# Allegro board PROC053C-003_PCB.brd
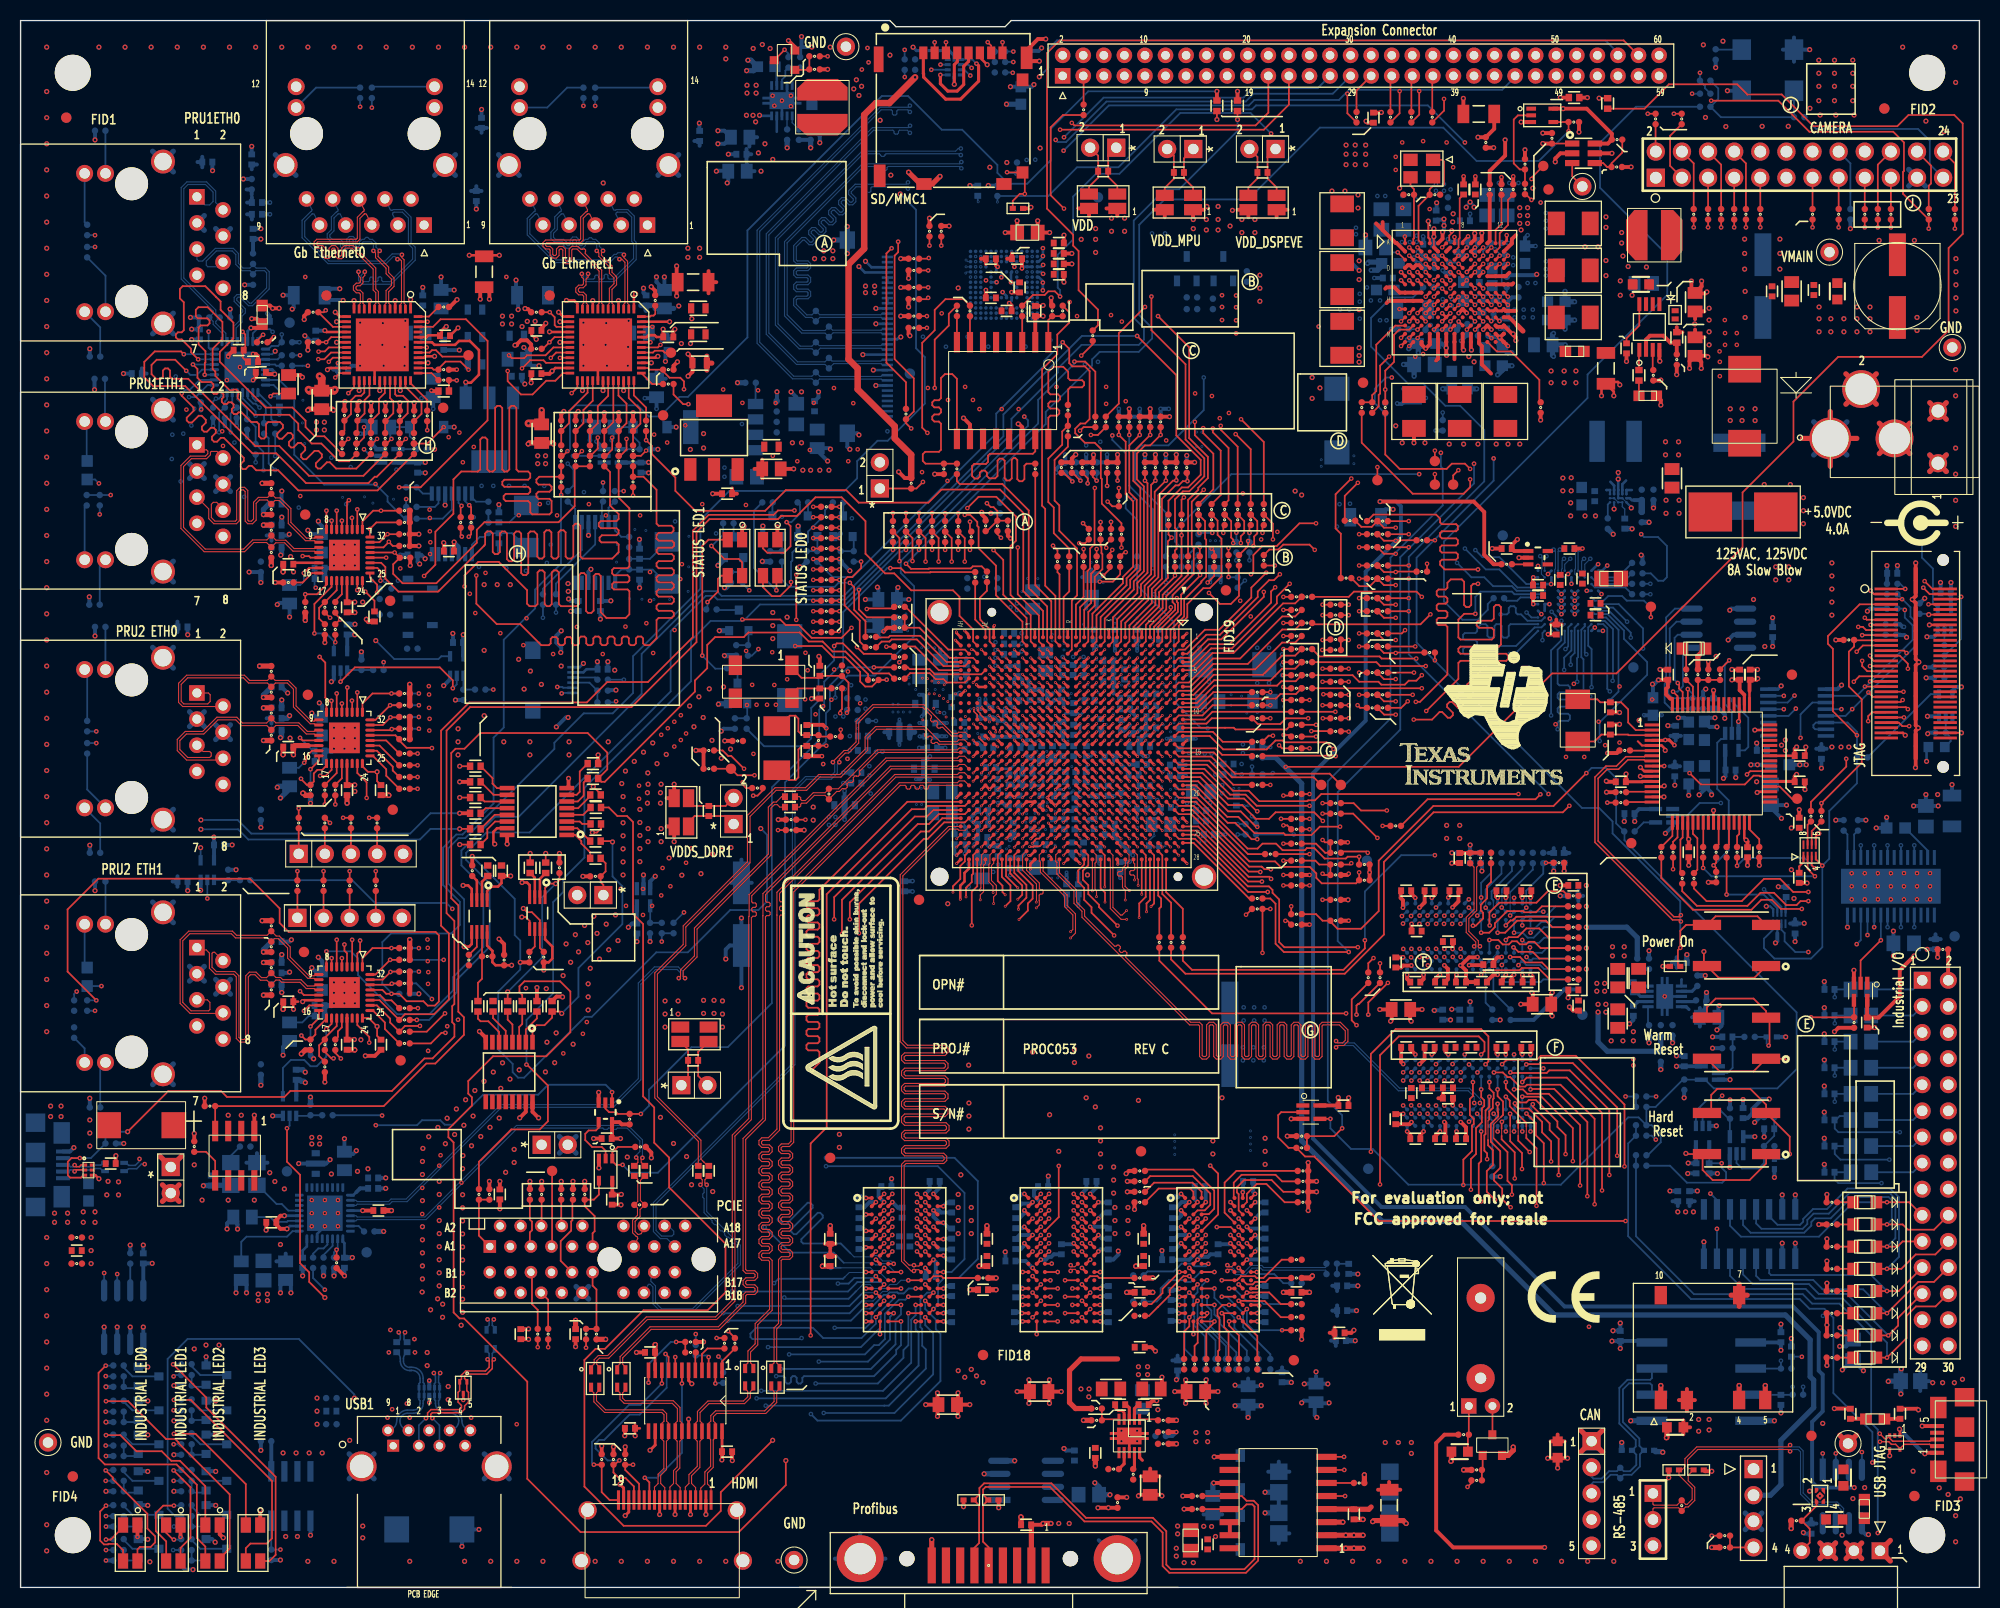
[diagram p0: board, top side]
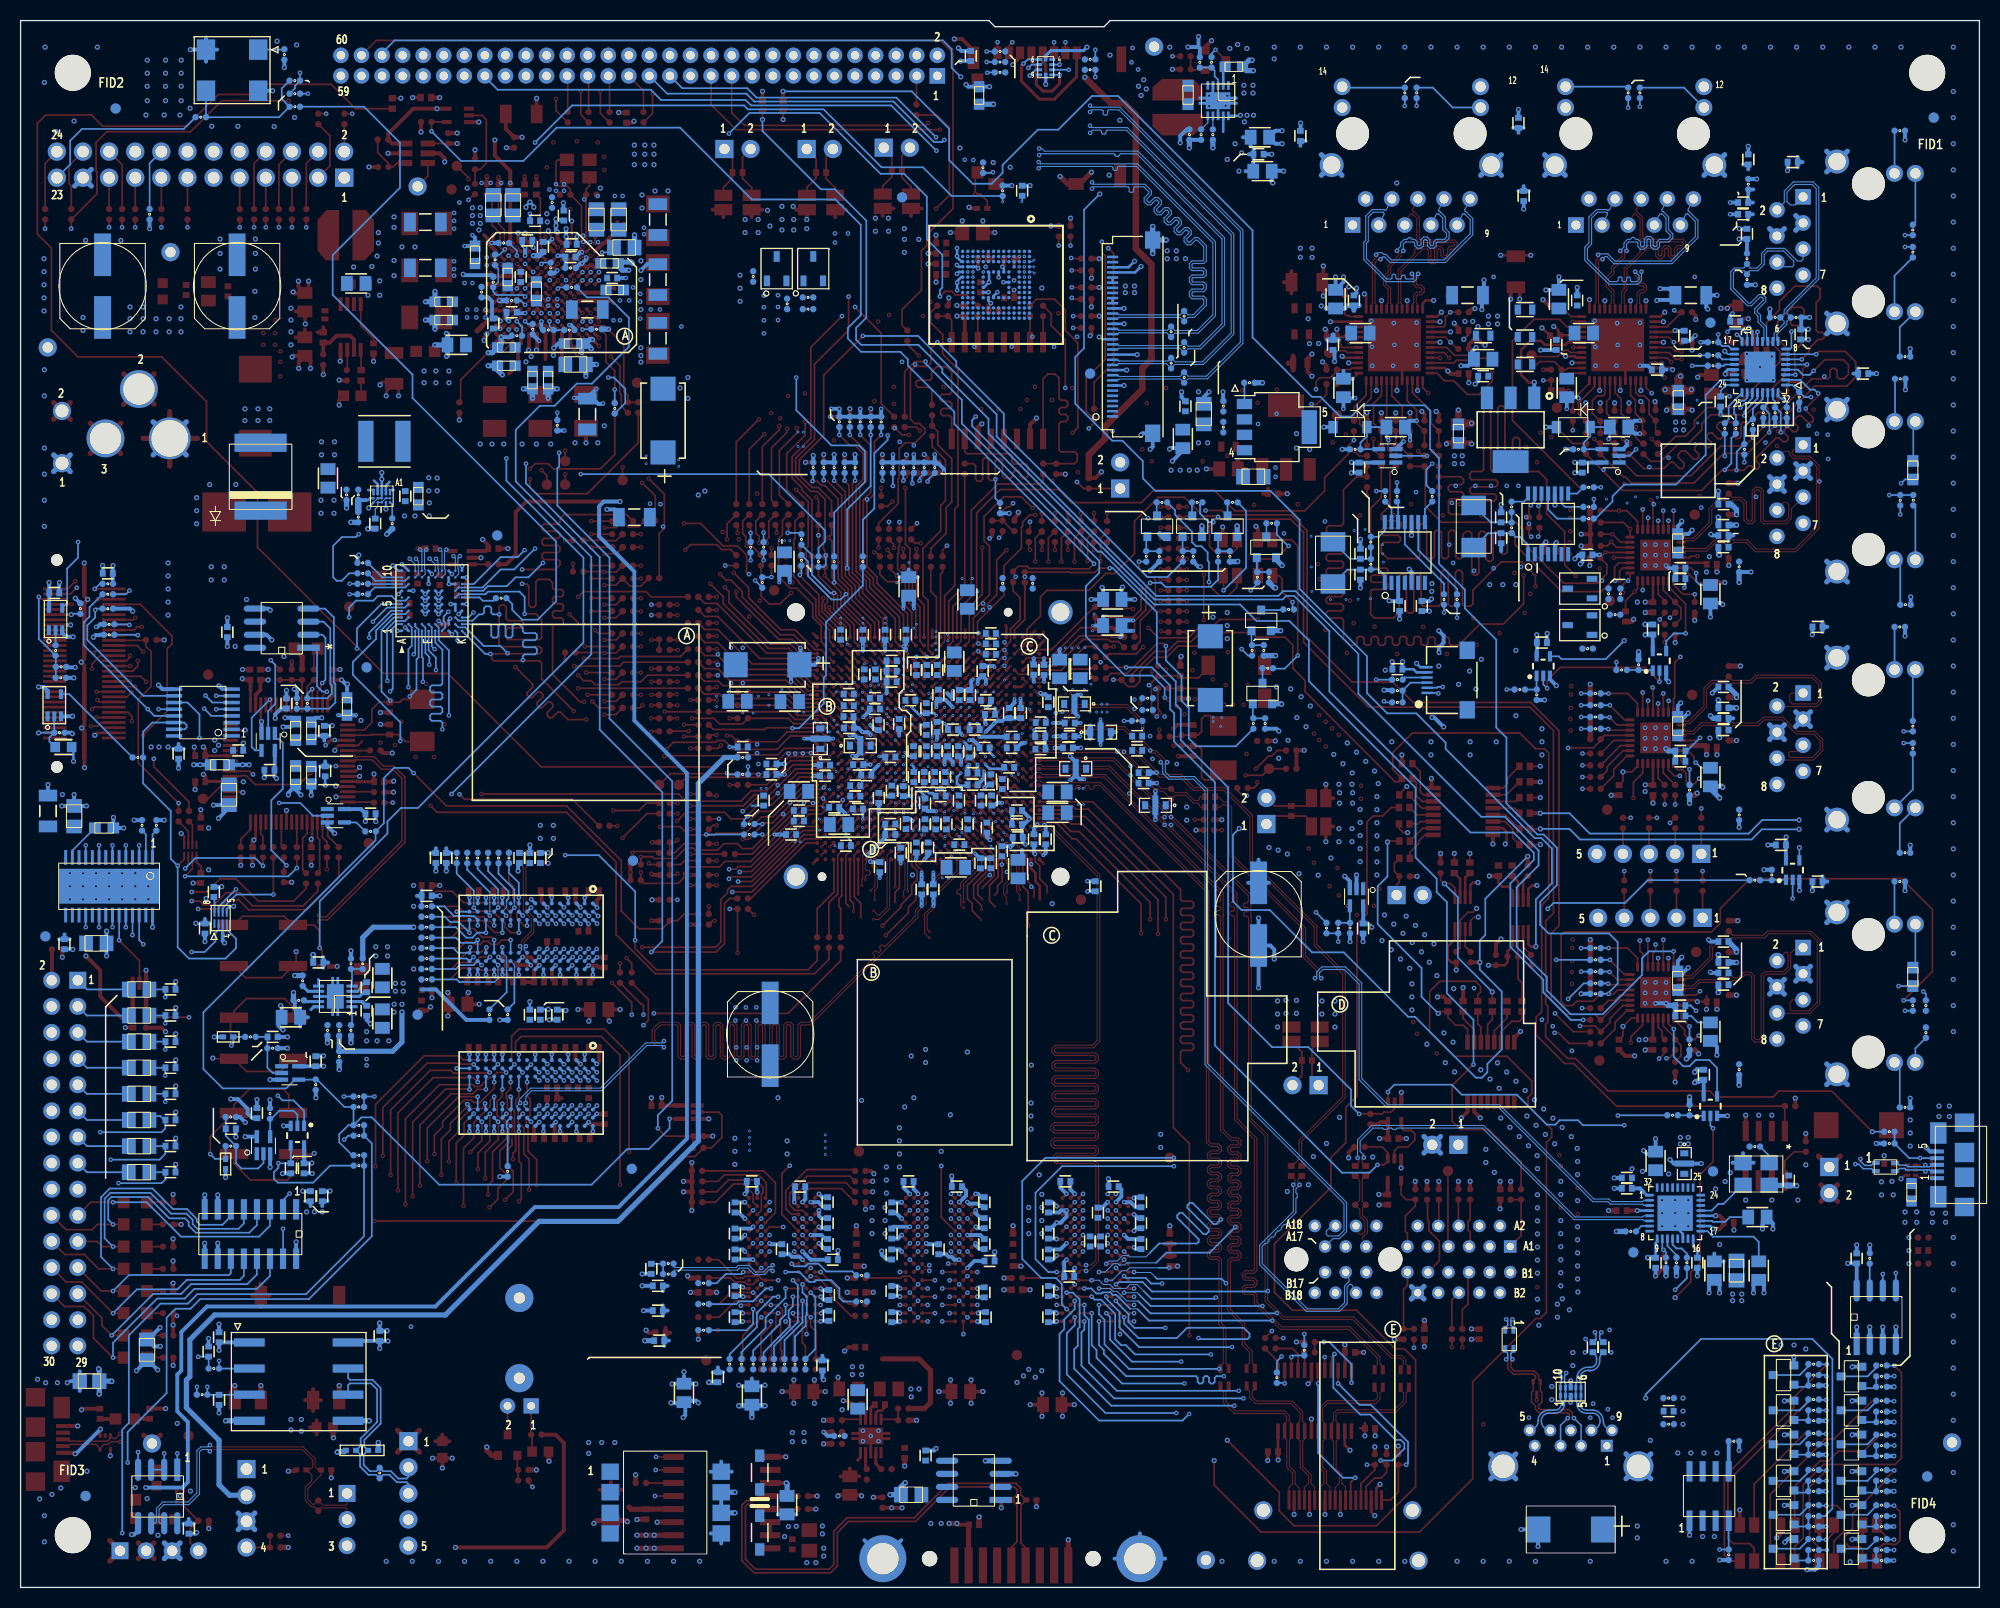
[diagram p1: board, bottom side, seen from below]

Outline 190.5 x 152.4 mm; copper layers: TOP, L2_GND1, L3_SIG1, L4_SIG2, L5_GND2, L6_PWR1, L7_PWR2, L8_GND3, L9_SIG3, L10_SIG4, L11_GND4, BOTTOM. Coordinates in mm from the lower left corner of the outline.
Outline path: 0,152.4 0,0 190.5,0 190.5,152.4 96.34,152.4 95.74,151.8 85.14,151.8 84.54,152.4 0,152.4

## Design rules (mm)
net group AM57XX_HDMI_CLK+: nets AM57XX_HDMI_CLK+ HDMI_CLK+
net group AM57XX_HDMI_CLK-: nets AM57XX_HDMI_CLK- HDMI_CLK-
net group AM57XX_HDMI_TX0+: nets AM57XX_HDMI_TX0+ HDMI_TX0+
net group AM57XX_HDMI_TX0-: nets AM57XX_HDMI_TX0- HDMI_TX0-
net group AM57XX_HDMI_TX1+: nets AM57XX_HDMI_TX1+ HDMI_TX1+
net group AM57XX_HDMI_TX1-: nets AM57XX_HDMI_TX1- HDMI_TX1-
net group AM57XX_HDMI_TX2+: nets AM57XX_HDMI_TX2+ HDMI_TX2+
net group AM57XX_HDMI_TX2-: nets AM57XX_HDMI_TX2- HDMI_TX2-
net group AM57XX_LCD_DE: nets AM57XX_LCD_DE LCD_DEN
net group AM57XX_LCD_HSYNC: nets AM57XX_LCD_HSYNC LCD_HS
net group AM57XX_LCD_PCLK: nets AM57XX_LCD_PCLK LCD_PCLK
net group AM57XX_LCD_VSYNC: nets AM57XX_LCD_VSYNC LCD_VS
net group AM57XX_MMC1_CLK: nets AM57XX_MMC1_CLK MMC_CLK
net group AM57XX_MMC1_CMD: nets AM57XX_MMC1_CMD MMC_CMD
net group AM57XX_MMC1_DAT0: nets AM57XX_MMC1_DAT0 MMC_D0
net group AM57XX_MMC1_DAT1: nets AM57XX_MMC1_DAT1 MMC_D1
net group AM57XX_MMC1_DAT2: nets AM57XX_MMC1_DAT2 MMC_D2
net group AM57XX_MMC1_DAT3: nets AM57XX_MMC1_DAT3 MMC_D3
net group AM57XX_PCIE_PER0: nets AM57XX_PCIE_PERN0 AM57XX_PCIE_PERP0
net group AM57XX_PCIE_PET0: nets AM57XX_PCIE_PETN0 AM57XX_PCIE_PETP0
net group AM57XX_PRU1ETH0_MRCLK: nets AM57XX_PRU1ETH0_MRCLK PRU1ETH0_RXCLK
net group AM57XX_PRU1ETH0_RXDV: nets AM57XX_PRU1ETH0_RXDV PRU1ETH0_RXDV
net group AM57XX_PRU1ETH1_TXCLK: nets AM57XX_PRU1ETH1_TXCLK PRU1ETH1_TXCLK
net group AM57XX_PRU1ETH1_TXD2: nets AM57XX_PRU1ETH1_TXD2 PRU1ETH1_TXD2
net group AM57XX_PRU1ETH1_TXD3: nets AM57XX_PRU1ETH1_TXD3 PRU1ETH1_TXD3
net group AM57XX_PRU1ETH1_TXEN: nets AM57XX_PRU1ETH1_TXEN PRU1ETH1_TXEN
net group AM57XX_PRU2ETH0_CRS: nets AM57XX_PRU2ETH0_CRS PRU2ETH0_CRS
net group AM57XX_PRU2ETH0_MRCLK: nets AM57XX_PRU2ETH0_MRCLK PRU2ETH0_RXCLK
net group AM57XX_PRU2ETH0_RXD0: nets AM57XX_PRU2ETH0_RXD0 PRU2ETH0_RXD0
net group AM57XX_PRU2ETH0_RXD1: nets AM57XX_PRU2ETH0_RXD1 PRU2ETH0_RXD1
net group AM57XX_PRU2ETH0_RXD2: nets AM57XX_PRU2ETH0_RXD2 PRU2ETH0_RXD2
net group AM57XX_PRU2ETH0_RXD3: nets AM57XX_PRU2ETH0_RXD3 PRU2ETH0_RXD3
net group AM57XX_PRU2ETH0_RXDV: nets AM57XX_PRU2ETH0_RXDV PRU2ETH0_RXDV
net group AM57XX_PRU2ETH0_RXER: nets AM57XX_PRU2ETH0_RXER PRU2ETH0_RXERR
net group AM57XX_PRU2ETH0_TXCLK: nets AM57XX_PRU2ETH0_TXCLK PRU2ETH0_TXCLK
net group AM57XX_PRU2ETH0_TXD0: nets AM57XX_PRU2ETH0_TXD0 PRU2ETH0_TXD0
net group AM57XX_PRU2ETH0_TXD1: nets AM57XX_PRU2ETH0_TXD1 PRU2ETH0_TXD1
net group AM57XX_PRU2ETH0_TXD2: nets AM57XX_PRU2ETH0_TXD2 PRU2ETH0_TXD2
net group AM57XX_PRU2ETH0_TXD3: nets AM57XX_PRU2ETH0_TXD3 PRU2ETH0_TXD3
net group AM57XX_PRU2ETH0_TXEN: nets AM57XX_PRU2ETH0_TXEN PRU2ETH0_TXEN
net group AM57XX_PRU2ETH1_COL: nets AM57XX_PRU2ETH1_COL PRU2ETH1_COL
net group AM57XX_PRU2ETH1_CRS: nets AM57XX_PRU2ETH1_CRS PRU2ETH1_CRS
net group AM57XX_PRU2ETH1_MRCLK: nets AM57XX_PRU2ETH1_MRCLK PRU2ETH1_RXCLK
net group AM57XX_PRU2ETH1_RXD0: nets AM57XX_PRU2ETH1_RXD0 PRU2ETH1_RXD0
net group AM57XX_PRU2ETH1_RXD1: nets AM57XX_PRU2ETH1_RXD1 PRU2ETH1_RXD1
net group AM57XX_PRU2ETH1_RXD2: nets AM57XX_PRU2ETH1_RXD2 PRU2ETH1_RXD2
net group AM57XX_PRU2ETH1_RXD3: nets AM57XX_PRU2ETH1_RXD3 PRU2ETH1_RXD3
net group AM57XX_PRU2ETH1_RXDV: nets AM57XX_PRU2ETH1_RXDV PRU2ETH1_RXDV
net group AM57XX_PRU2ETH1_RXER: nets AM57XX_PRU2ETH1_RXER PRU2ETH1_RXERR
net group AM57XX_PRU2ETH1_TXCLK: nets AM57XX_PRU2ETH1_TXCLK PRU2ETH1_TXCLK
net group AM57XX_PRU2ETH1_TXD0: nets AM57XX_PRU2ETH1_TXD0 PRU2ETH1_TXD0
net group AM57XX_PRU2ETH1_TXD1: nets AM57XX_PRU2ETH1_TXD1 PRU2ETH1_TXD1
net group AM57XX_PRU2ETH1_TXD2: nets AM57XX_PRU2ETH1_TXD2 PRU2ETH1_TXD2
net group AM57XX_PRU2ETH1_TXD3: nets AM57XX_PRU2ETH1_TXD3 PRU2ETH1_TXD3
net group AM57XX_PRU2ETH1_TXEN: nets AM57XX_PRU2ETH1_TXEN PRU2ETH1_TXEN
net group AM57XX_RGMII1_RD1: nets AM57XX_RGMII1_RD1 ETH1_RXD1
net group AM57XX_RGMII1_RD2: nets AM57XX_RGMII1_RD2 ETH1_RXD2
net group AM57XX_RTCK: nets AM57XX_RTCK RTCK
net group AM57XX_VOUT1_D0: nets AM57XX_VOUT1_D0 LCD_B0
net group AM57XX_VOUT1_D1: nets AM57XX_VOUT1_D1 LCD_B1
net group AM57XX_VOUT1_D8: nets AM57XX_VOUT1_D8 LCD_G0
net group AM57XX_VOUT1_D9: nets AM57XX_VOUT1_D9 LCD_G1
net group AM57XX_VOUT1_D16: nets AM57XX_VOUT1_D16 LCD_R0
net group AM57XX_VOUT1_D17: nets AM57XX_VOUT1_D17 LCD_R1
net group AM437X_USB1_D: nets AM574X_USB2_DM AM574X_USB2_DP
net group AM574X_QSPI_D1: nets AM574X_QSPI_D1 SPIMEM_D1
net group AM574X_VIN4B_DATA0: nets AM574X_VIN4B_DATA0 CAM1_DATA0
net group AM574X_VIN4B_DATA1: nets AM574X_VIN4B_DATA1 CAM1_DATA1
net group AM574X_VIN4B_DATA2: nets AM574X_VIN4B_DATA2 CAM1_DATA2
net group AM574X_VIN4B_DATA3: nets AM574X_VIN4B_DATA3 CAM1_DATA3
net group AM574X_VIN4B_DATA4: nets AM574X_VIN4B_DATA4 CAM1_DATA4
net group AM574X_VIN4B_DATA5: nets AM574X_VIN4B_DATA5 CAM1_DATA5
net group AM574X_VIN4B_DATA6: nets AM574X_VIN4B_DATA6 CAM1_DATA6
net group AM574X_VIN4B_DATA7: nets AM574X_VIN4B_DATA7 CAM1_DATA7
net group AM574X_VIN4B_HSYNC: nets AM574X_VIN4B_HSYNC CAM1_HSYNC
net group AM574X_VIN4B_PCLK: nets AM574X_VIN4B_PCLK CAM1_PCLK
net group AM574X_VIN4B_VSYNC: nets AM574X_VIN4B_VSYNC CAM1_VSYNC
net group ETH_MDIO_CLK: nets ETH_MDIO_CLK PRU1ETH0_COL
net group JTAG_TCK: nets JTAG_TCK TCK
net group PCI_CONN_REF: nets PCI_CONN_REFN PCI_CONN_REFP
net group SERDES_REF_CLK: nets SERDES_REF_CLKN SERDES_REF_CLKP
net group SPIMEM_CSN: nets AM574X_QSPI_CSN SPIMEM_CSN
net group SPIMEM_D0: nets AM574X_QSPI_D0 SPIMEM_D0
net group SPIMEM_D2: nets AM574X_QSPI_D2 SPIMEM_D2
net group SPIMEM_D3: nets AM574X_QSPI_D3 SPIMEM_D3
net group AM57XX_PRU1ETH1_MRCLK: nets AM57XX_PRU1ETH1_MRCLK ETH1_TXD3 PRU1ETH1_RXCLK
net group AM57XX_PRU1ETH1_TXD0: nets AM57XX_PRU1ETH1_TXD0 ETH1_TXEN PRU1ETH1_TXD0
net group AM57XX_PRU1ETH1_TXD1: nets AM57XX_PRU1ETH1_TXD1 ETH1_TXCLK PRU1ETH1_TXD1
net group AM57XX_PRU1ETH_MDCLK: nets AM57XX_PRU1ETH_MDCLK PRU1ETH0_MDC PRU1ETH1_MDC
net group AM57XX_PRU1ETH_MDDATA: nets AM57XX_PRU1ETH_MDDATA PRU1ETH0_MDIO PRU1ETH1_MDIO
net group AM57XX_PRU2ETH_MDCLK: nets AM57XX_PRU2ETH_MDCLK PRU2ETH0_MDC PRU2ETH1_MDC
net group AM57XX_PRU2ETH_MDDATA: nets AM57XX_PRU2ETH_MDDATA PRU2ETH0_MDIO PRU2ETH1_MDIO
net group AM57XX_RGMII0_RD0: nets AM57XX_RGMII0_RD0 ETH0_RXD0 PRU1ETH0_TXD0
net group AM57XX_RGMII0_RD1: nets AM57XX_RGMII0_RD1 ETH0_RXD1 PRU1ETH0_TXD1
net group AM57XX_RGMII0_RD2: nets AM57XX_RGMII0_RD2 ETH0_RXD2 PRU1ETH0_TXEN
net group AM57XX_RGMII0_RD3: nets AM57XX_RGMII0_RD3 ETH0_RXD3 PRU1ETH0_TXD2
net group AM57XX_RGMII0_RXCLK: nets AM57XX_RGMII0_RXCLK ETH0_RXCLK PRU1ETH0_TXCLK
net group AM57XX_RGMII0_RXCTL: nets AM57XX_RGMII0_RXCTL ETH0_RXDV PRU1ETH0_TXD3
net group AM57XX_RGMII0_TD0: nets AM57XX_RGMII0_TD0 ETH0_TXD0 PRU1ETH0_RXD0
net group AM57XX_RGMII0_TD1: nets AM57XX_RGMII0_TD1 ETH0_TXD1 PRU1ETH0_RXD1
net group AM57XX_RGMII0_TD2: nets AM57XX_RGMII0_TD2 ETH0_TXD2 PRU1ETH0_RXERR
net group AM57XX_RGMII0_TD3: nets AM57XX_RGMII0_TD3 ETH0_TXD3 PRU1ETH0_CRS
net group AM57XX_RGMII0_TXCLK: nets AM57XX_RGMII0_TXCLK ETH0_TXCLK PRU1ETH0_RXD3
net group AM57XX_RGMII0_TXCTL: nets AM57XX_RGMII0_TXCTL ETH0_TXEN PRU1ETH0_RXD2
net group AM57XX_RGMII1_RD0: nets AM57XX_RGMII1_RD0 ETH1_RXD0 PRU1ETH1_CRS
net group AM57XX_RGMII1_RD3: nets AM57XX_RGMII1_RD3 ETH1_RXD3 PRU1ETH1_RXERR
net group AM57XX_RGMII1_RXCLK: nets AM57XX_RGMII1_RXCLK ETH1_RXCLK PRU1ETH1_RXD1
net group AM57XX_RGMII1_RXCTL: nets AM57XX_RGMII1_RXCTL ETH1_RXDV PRU1ETH1_RXD0
net group AM57XX_RGMII1_TD0: nets AM57XX_RGMII1_TD0 ETH1_TXD0 PRU1ETH1_RXD2
net group AM57XX_RGMII1_TD1: nets AM57XX_RGMII1_TD1 ETH1_TXD1 PRU1ETH1_RXD3
net group AM57XX_RGMII1_TD2: nets AM57XX_RGMII1_TD2 ETH1_TXD2 PRU1ETH1_RXDV
net group AM57XX_VOUT1_D2: nets AM57XX_VOUT1_D2 EMU2 LCD_B2
net group AM57XX_VOUT1_D3: nets AM57XX_VOUT1_D3 EMU5 LCD_B3
net group AM57XX_VOUT1_D4: nets AM57XX_VOUT1_D4 EMU6 LCD_B4
net group AM57XX_VOUT1_D5: nets AM57XX_VOUT1_D5 EMU7 LCD_B5
net group AM57XX_VOUT1_D6: nets AM57XX_VOUT1_D6 EMU8 LCD_B6
net group AM57XX_VOUT1_D7: nets AM57XX_VOUT1_D7 EMU9 LCD_B7
net group AM57XX_VOUT1_D10: nets AM57XX_VOUT1_D10 EMU3 LCD_G2
net group AM57XX_VOUT1_D11: nets AM57XX_VOUT1_D11 EMU10 LCD_G3
net group AM57XX_VOUT1_D12: nets AM57XX_VOUT1_D12 EMU11 LCD_G4
net group AM57XX_VOUT1_D13: nets AM57XX_VOUT1_D13 EMU12 LCD_G5
net group AM57XX_VOUT1_D14: nets AM57XX_VOUT1_D14 EMU13 LCD_G6
net group AM57XX_VOUT1_D15: nets AM57XX_VOUT1_D15 EMU14 LCD_G7
net group AM57XX_VOUT1_D18: nets AM57XX_VOUT1_D18 EMU4 LCD_R2
net group AM57XX_VOUT1_D19: nets AM57XX_VOUT1_D19 EMU15 LCD_R3
net group AM57XX_VOUT1_D20: nets AM57XX_VOUT1_D20 EMU16 LCD_R4
net group AM57XX_VOUT1_D21: nets AM57XX_VOUT1_D21 EMU17 LCD_R5
net group AM57XX_VOUT1_D22: nets AM57XX_VOUT1_D22 EMU18 LCD_R6
net group AM57XX_VOUT1_D23: nets AM57XX_VOUT1_D23 EMU19 LCD_R7
net group CLK: nets AM57XX_CLKOUT3 AM57XX_OSC0_IN AM57XX_OSC0_OUT ETH0GB_25MHZCLK ETH1GB_25MHZCLK INDUS_INPUTCLK N17745710 N22642197 OSC0_OUT PRU1ETH0_25MHZCLK PRU1ETH1_25MHZCLK PRU2ETH0_25MHZCLK PRU2ETH1_25MHZCLK SRCCLK XTIN XTOUT
net group DDR_ADD: nets DDR_CKE
net group PWR: nets ETH0_LDO_O N11219802 N11219922 N18915671 N18915723 N19923825 N19923832 N19923845 N19923851 N19923852 N19923865 N20287248 N21553219 N21553307 N21553371 N22644059 USB1_OVRCURN V5_0DFB VANA_OUT VLDO1_OUT VPP_CONN
net group SPIMEM_CLK: nets AM574X_QSPI_CLK AM574X_QSPI_RTCLK QSPI_CLK SPIMEM_CLK
nets with their own width: min track width 0.127; nets DGND
nets with their own width: min track width 0.381; nets VSDMMC

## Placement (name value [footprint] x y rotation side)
C1  18 pF  [CC0402]  76.45 83.39 90 top
C1_1  1uF  [CC0603]  177.27 10.68 90 top
C2  18 pF  [CC0402]  76.45 81.36 270 top
C2_1  1uF  [CC0603]  176.38 6.62 0 top
C3  10000pF  [CC0402]  167.51 46.14 90 bottom
C4  1uF  [CC0402]  170.05 44.61 180 bottom
C5  1uF  [CC0402]  165.99 53.55 180 bottom
C6  10uF  [CC0805]  93.49 69.87 270 bottom
C7  10000pF  [CC0402]  93.52 72.95 180 bottom
C8  10000pF  [CC0402]  93.6 74.22 180 bottom
C9  10000pF  [CC0402]  95.07 71.61 270 bottom
C10  10000pF  [CC0402]  97.16 70.44 270 bottom
C11  10000pF  [CC0402]  93.6 75.57 180 bottom
C12  10000pF  [CC0402]  90.8 72.77 90 bottom
C13  10uF  [CC0805]  110.9 74.2 0 bottom
C14  10000pF  [CC0402]  103.38 71.96 270 bottom
C15  10000pF  [CC0402]  110.24 72.14 0 bottom
C16  10000pF  [CC0402]  109.07 75.72 0 bottom
C17  10000pF  [CC0402]  102.23 71.96 270 bottom
C20  0.1uF  [CC0402]  170.33 126.07 90 top
C21  0.1uF  [CC0402]  174.4 126.19 90 top
C22  10uF  [CC0805]  172.24 126.07 90 top
C23  1uF  [CC0603]  176.68 126.07 90 top
C24  100uF  [SM-7351-CAP-SMDCAN]  169.44 126.57 270 bottom
C25  27pF  [SM-7351-CAP-0402]  135 135.46 0 top
C26  27pF  [SM-7351-CAP-0402]  137.54 135.46 180 top
C27  0.1uF  [CC0402]  140.34 135.97 270 top
C28  10000pF  [CC0402]  98.68 124.16 90 top
C29  10000pF  [CC0402]  81.53 35.43 270 bottom
C30  10000pF  [CC0402]  84.2 38.99 0 bottom
C31  10000pF  [CC0402]  81.53 37.46 270 bottom
C32  10000pF  [CC0402]  90.55 36.96 90 bottom
C33  22uF  [CC0805]  90.17 17.78 0 top
C34  10000pF  [CC0402]  88.9 39.5 0 bottom
C35  10000pF  [CC0402]  90.55 26.29 270 bottom
C36  10000pF  [CC0402]  90.55 32.38 90 bottom
C37  10000pF  [CC0402]  90.55 28.83 90 bottom
C38  10000pF  [CC0402]  90.55 34.42 270 bottom
C39  10000pF  [CC0402]  88.52 30.23 0 bottom
C40  10000pF  [CC0402]  85.47 33.66 90 bottom
C41  10000pF  [CC0402]  85.72 36.45 90 bottom
C42  10000pF  [CC0402]  81.53 33.4 270 bottom
C43  10000pF  [CC0402]  86.49 33.66 90 bottom
C44  0.1uF  [CC0402]  78.74 33.91 270 top
C45  0.1uF  [CC0402]  78.74 31.75 270 top
C46  0.1uF  [CC0402]  93.6 28.96 0 top
C47  0.1uF  [CC0402]  109.22 33.91 270 top
C48  10000pF  [CC0402]  105.79 36.96 90 bottom
C49  10000pF  [CC0402]  96.77 37.46 270 bottom
C50  10000pF  [CC0402]  104.14 39.5 0 bottom
C51  10000pF  [CC0402]  96.65 26.29 270 bottom
C52  22uF  [CC0805]  99.06 19.05 0 top
C53  0.1uF  [CC0402]  109.22 31.75 270 top
C54  0.1uF  [CC0402]  124.08 28.7 0 top
C55  10000pF  [CC0402]  105.79 26.29 270 bottom
C56  10000pF  [CC0402]  96.27 31.75 180 bottom
C57  10000pF  [CC0402]  96.77 28.7 90 bottom
C58  10000pF  [CC0402]  101.22 32.89 270 bottom
C59  10000pF  [CC0402]  96.77 33.4 270 bottom
C60  10000pF  [CC0402]  111.51 31.88 180 bottom
C61  10000pF  [CC0402]  121.03 32.38 270 bottom
C62  10000pF  [CC0402]  116.46 32.89 270 bottom
C63  10000pF  [CC0402]  119.38 39.5 0 bottom
C64  22uF  [CC0805]  114.3 19.05 0 top
C65  10000pF  [CC0402]  105.79 32.38 270 bottom
C66  10000pF  [CC0402]  105.79 28.83 90 bottom
C67  10000pF  [CC0402]  96.77 35.43 270 bottom
C68  10000pF  [CC0402]  105.79 34.42 270 bottom
C69  10000pF  [CC0402]  99.44 38.99 0 bottom
C70  10000pF  [CC0402]  121.03 26.29 270 bottom
C71  10000pF  [CC0402]  114.68 38.99 0 bottom
C72  10000pF  [CC0402]  111.89 26.42 270 bottom
C73  10000pF  [CC0402]  121.03 34.42 270 bottom
C74  10000pF  [CC0402]  112.01 37.46 270 bottom
C75  10000pF  [CC0402]  121.03 28.83 90 bottom
C76  10000pF  [CC0402]  121.03 36.96 90 bottom
C77  10000pF  [CC0402]  112.01 35.43 270 bottom
C78  10000pF  [CC0402]  112.01 33.4 270 bottom
C79  10000pF  [CC0402]  111.89 28.45 90 bottom
C80  0.1uF  [CC0402]  93.98 33.91 270 top
C81  10000pF  [CC0402]  96.14 78.59 90 bottom
C82  0.1uF  [CC0402]  93.98 31.75 270 top
C83  0.1uF  [CC0402]  108.84 28.7 0 top
C84  0.001uF  [SM-7351-CAP-0402]  110.87 14.73 180 bottom
C85  0.1uF  [CC0402]  129.16 30.99 270 bottom
C86  0.001uF  [SM-7351-CAP-0402]  111.12 16.26 0 top
C87  0.1uF  [CC0402]  128.52 29.34 0 bottom
C88  10uF  [CC0805]  109.86 9.91 270 top
C89  0.1uF  [CC0402]  128.27 24.77 0 top
C90  0.1uF  [CC0402]  109.22 17.78 0 top
C91  10uF  [CC0805]  109.98 19.3 0 top
C92  10uF  [CC0805]  109.09 18.29 270 bottom
C93  0.1uF  [CC0402]  108.84 23.37 0 top
C94  0.1uF  [CC0402]  112.52 21.59 270 bottom
C95  10uF  [CC0805]  125.98 18.92 270 bottom
C96  10uF  [CC0805]  119.38 18.67 270 bottom
C97  10uF  [CC0805]  106.05 19.3 180 top
C98  0.1uF  [CC0402]  128.4 24 0 bottom
C99  0.1uF  [CC0402]  104.52 13.08 270 top
C100  0.1uF  [CC0402]  106.93 17.78 180 top
C101  10pF  [SM-7351-CAP-0402]  104.65 16.26 180 top
C102  0.1uF  [CC0402]  22.99 134.7 0 bottom
C103  0.1uF  [CC0402]  22.99 133.56 0 bottom
C104  0.1uF  [CC0402]  17.4 121.87 270 bottom
C105  10000pF  [CC0402]  23.37 118.19 180 top
C106  4700pF  [CC0402]  18.16 138.64 180 bottom
C107  0.1uF  [CC0402]  22.61 131.65 90 bottom
C108  0.1uF  [CC0402]  25.17 115.35 270 bottom
C109  0.1uF  [CC0402]  22.61 119.21 0 top
C110  10uF  [CC0805]  26.06 117.02 90 top
C111  0.1uF  [CC0402]  21.21 120.35 180 top
C112  10000pF  [CC0402]  23.75 123.14 0 bottom
C113  10000pF  [CC0402]  42.55 91.9 180 bottom
C114  10000pF  [CC0402]  97.92 79.2 180 bottom
C115  10000pF  [CC0402]  96.14 70.44 270 bottom
C116  0.1uF  [CC0402]  24.89 102.32 0 bottom
C117  0.1uF  [CC0402]  24.89 101.17 0 bottom
C118  10000pF  [CC0402]  26.03 99.52 180 top
C119  0.1uF  [CC0402]  24.89 105.36 0 bottom
C120  10000pF  [CC0402]  31.75 95.33 270 top
C121  4700pF  [CC0402]  11.3 118.06 0 bottom
C122  0.1uF  [CC0402]  24.89 103.33 0 bottom
C123  0.1uF  [CC0402]  34.42 94.44 270 top
C124  0.1uF  [CC0402]  29.08 99.14 0 bottom
C125  10uF  [CC0805]  26.16 96.6 270 bottom
C126  0.1uF  [CC0402]  29.08 98.13 0 bottom
C127  10000pF  [CC0402]  31.75 93.17 90 bottom
C128  0.1uF  [CC0402]  24.89 84.54 0 bottom
C129  0.1uF  [CC0402]  24.89 83.39 0 bottom
C130  10000pF  [CC0402]  31.75 77.55 270 top
C131  4700pF  [CC0402]  15.75 93.43 180 bottom
C132  0.1uF  [CC0402]  24.89 85.55 0 bottom
C133  0.1uF  [CC0402]  24.89 87.58 0 bottom
C134  0.1uF  [CC0402]  29.08 80.35 0 bottom
C135  0.1uF  [CC0402]  35.05 77.55 270 top
C136  10uF  [CC0805]  26.16 78.82 270 bottom
C137  10000pF  [CC0402]  26.03 81.74 180 top
C138  0.1uF  [CC0402]  29.08 81.36 0 bottom
C139  10000pF  [CC0402]  19.3 72.22 0 bottom
C140  0.1uF  [CC0402]  24.89 59.77 0 bottom
C141  0.1uF  [CC0402]  24.89 58.63 0 bottom
C142  10000pF  [CC0402]  26.03 56.98 180 top
C143  0.1uF  [CC0402]  24.89 60.79 0 bottom
C144  10000pF  [CC0402]  31.75 52.79 270 top
C145  0.1uF  [CC0402]  24.89 62.82 0 bottom
C146  4700pF  [CC0402]  15.75 68.66 180 bottom
C147  0.1uF  [CC0402]  35.05 52.79 270 top
C148  0.1uF  [CC0402]  29.08 56.6 0 bottom
C149  10uF  [CC0805]  26.16 54.06 270 bottom
C150  0.1uF  [CC0402]  29.08 55.58 0 bottom
C151  10000pF  [CC0402]  26.8 49.87 90 bottom
C152  10000pF  [CC0402]  131.57 142.96 90 top
C153  0.1uF  [CC0402]  48.26 117.81 0 bottom
C154  10uF  [CC0805]  48.26 119.46 0 bottom
C155  0.1uF  [CC0402]  28.7 121.75 270 bottom
C156  10uF  [CC0805]  29.29 115.5 270 top
C157  47uF  [CC1206]  28.07 125.68 0 bottom
C158  47uF  [CC1206]  45.09 127.97 90 top
C159  10uF  [CC0805]  40.13 116.67 270 bottom
C160  0.1uF  [CC0402]  31.37 118.45 0 bottom
C161  10uF  [CC0805]  40.89 125.3 90 bottom
C162  0.1uF  [CC0402]  39.12 125.18 90 bottom
C163  10uF  [CC0805]  38.48 122 180 bottom
C164  0.1uF  [CC0402]  41.15 120.86 270 bottom
C165  10000pF  [CC0402]  41.27 121.75 0 top
C166  0.1uF  [CC0402]  22.48 138.89 270 bottom
C167  0.1uF  [CC0402]  44.32 135.34 90 bottom
C168  10uF  [CC0805]  35.05 112.86 180 bottom
C169  10000pF  [CC0402]  41.66 100.79 180 top
C170  10000pF  [CC0402]  38.13 100.44 180 bottom
C171  10000pF  [CC0402]  38.61 108.92 270 bottom
C172  18pF  [CC0402]  46.51 102.05 90 bottom
C173  18pF  [CC0402]  46.51 104.08 270 bottom
C174  0.1uF  [CC0402]  50.16 122.26 180 top
C175  10uF  [CC0805]  50.67 112.22 270 top
C176  0.1uF  [CC0402]  68.71 106.38 180 top
C177  10uF  [CC0805]  73.02 108.79 0 top
C178  47uF  [CC1206]  49.78 125.68 180 bottom
C179  47uF  [CC1206]  65.41 126.95 180 top
C180  10uF  [CC0805]  61.85 116.67 270 bottom
C181  0.1uF  [CC0402]  50.16 118.06 180 top
C182  10uF  [CC0805]  62.61 125.3 90 bottom
C183  0.1uF  [CC0402]  60.83 125.18 90 bottom
C184  10uF  [CC0805]  60.2 122 180 bottom
C185  0.1uF  [CC0402]  62.86 120.86 270 bottom
C186  10000pF  [CC0402]  62.99 121.62 0 top
C187  0.1uF  [CC0402]  44.83 142.45 270 bottom
C188  0.1uF  [CC0402]  66.04 141.18 270 bottom
C189  10uF  [CC0805]  56.77 112.86 180 bottom
C190  10000pF  [CC0402]  56.39 95.46 270 bottom
C191  10000pF  [CC0402]  54.23 95.46 270 bottom
C192  10000pF  [CC0402]  60.32 108.92 270 bottom
C193  18pF  [CC0402]  60.2 98.51 90 bottom
C194  18pF  [CC0402]  60.2 100.54 270 bottom
C195  10000pF  [CC0402]  179.58 54.95 270 top
C196  0.001uF  [SM-7351-CAP-0402]  186.94 62.06 180 top
C197  0.022uF  [CC0402]  175.92 58.17 180 bottom
C198  0.022uF  [CC0402]  175.92 55.63 180 bottom
C199  0.022uF  [CC0402]  175.92 53.09 180 bottom
C200  0.022uF  [CC0402]  175.92 50.55 180 bottom
C201  0.022uF  [CC0402]  175.92 48.01 180 bottom
C202  0.022uF  [CC0402]  175.92 45.47 180 bottom
C203  0.022uF  [CC0402]  175.92 42.93 180 bottom
C204  0.022uF  [CC0402]  175.92 40.39 180 bottom
C205  2.2uF  [SM-7351-CAP-0805]  183.13 62.65 180 bottom
C206  10uF  [CC1206]  187.83 75.52 90 bottom
C207  10000pF  [CC0402]  186.23 62.57 270 bottom
C208  2.2uF  [SM-7351-CAP-0805]  178.21 23.11 90 bottom
C209  1uF  [CC0402]  161.16 38.05 90 bottom
C210  10000pF  [CC0402]  162.31 38.05 90 bottom
C211  0.1uF  [CC0402]  98.08 148.96 270 bottom
C212  4.7uF  [SM-7351-CAP-0603]  97.28 145.12 270 bottom
C213  0.1uF  [CC0402]  164.21 40.77 270 bottom
C214  10000pF  [CC0402]  128.65 46.86 0 top
C215  10uF  [CC0805]  69.72 137.75 180 bottom
C216  10000pF  [CC0402]  70.1 139.4 180 bottom
C217  4.7uF  [SM-7351-CAP-0603]  72.52 147.91 180 bottom
C218  4.7uF  [CC0805]  69.98 141.05 180 bottom
C219  10000pF  [CC0402]  56.61 89.31 0 bottom
C220  10000pF  [CC0402]  11.94 32 90 bottom
C221  10000pF  [CC0402]  182.02 98.63 0 bottom
C222  10uF  [CC0805]  77.47 111.71 270 bottom
C223  DNI  [SM-7351-CAP-0402]  186.56 89.53 180 bottom
C224  2.2uF  [SM-7351-CAP-0805]  170.23 77.09 270 bottom
C225  10000pF  [CC0402]  182.78 16.89 90 top
C226  10000pF  [CC0402]  177.95 16.89 90 top
C227  10000pF  [CC0402]  173.02 78.36 0 top
C228  10000pF  [CC0402]  166.29 79.51 180 bottom
C229  10000pF  [CC0402]  167.94 71.51 270 top
C230  10000pF  [CC0402]  156.46 75.27 0 bottom
C231  4.7uF  [SM-7351-CAP-0603]  162.23 83.32 270 bottom
C232  10000pF  [CC0402]  168.2 88.78 90 top
C233  10000pF  [CC0402]  173.02 80.9 0 top
C234  10000pF  [CC0402]  160.96 83.32 270 bottom
C235  10000pF  [CC0402]  160.2 88.78 90 top
C236  10000pF  [CC0402]  164.64 85.98 270 bottom
C237  4.7uF  [SM-7351-CAP-0603]  162.23 79 90 bottom
C238  10000pF  [CC0402]  155.63 78.36 180 top
C239  10000pF  [CC0402]  162.23 71.51 270 top
C240  10000pF  [CC0402]  160.87 79.38 90 bottom
C241  4.7uF  [SM-7351-CAP-0603]  158.75 85.68 270 bottom
C242  10000pF  [CC0402]  167.18 88.78 270 top
C243  18pF  [CC0402]  154.61 85.6 270 top
C244  18pF  [CC0402]  154.61 83.44 90 top
C245  0.1uF  [CC0402]  170.39 92.92 90 bottom
C246  15pF  [CC0402]  77.72 89.15 90 top
C247  15pF  [CC0402]  77.72 86.95 270 top
C248  10000pF  [CC0402]  59.94 64.09 270 bottom
C249  3.3uF  [CC0603]  160.91 15.58 180 top
C250  3.3uF  [CC0603]  149.48 13.42 270 top
C251  10000pF  [CC0402]  171.2 24.34 90 bottom
C252  0.1uF  [CC0402]  155.58 24.47 90 bottom
C253  100pF  [CC0402]  172.21 22.94 90 bottom
C254  100pF  [CC0402]  171.2 18.24 270 bottom
C255  10000pF  [CC0402]  94.36 125.43 0 top
C256  10000pF  [CC0402]  95.89 124.16 180 top
C257  10000pF  [CC0402]  94.36 129.24 180 top
C258  10000pF  [CC0402]  97.16 126.45 90 top
C261  10000pF  [CC0402]  100.97 128.73 0 top
C262  10000pF  [CC0402]  100.97 129.75 0 top
C263  10000pF  [CC0402]  100.97 130.76 0 top
C264  10000pF  [CC0402]  100.97 127.72 0 top
C265  1uF  [CC0402]  93.09 135.84 90 bottom
C266  10uF  [CC0805]  89.46 89.34 90 bottom
C267  10000pF  [CC0402]  99.21 86.8 90 bottom
C268  47uF  [CC1206]  135.38 114.13 90 bottom
C269  47uF  [CC1206]  128.52 133.05 270 bottom
C270  47uF  [CC1206]  130.81 104.09 180 bottom
C271  47uF  [CC1206]  135.38 124.29 180 bottom
C272  4.7uF  [SM-7351-CAP-0603]  136.78 120.99 180 bottom
C273  4.7uF  [SM-7351-CAP-0603]  132.72 126.19 180 bottom
C274  4.7uF  [SM-7351-CAP-0603]  143.26 120.6 0 bottom
C275  4.7uF  [SM-7351-CAP-0603]  143.26 118.83 0 bottom
C276  47uF  [CC1206]  151.13 132.8 180 bottom
C277  47uF  [CC1206]  151.13 128.35 180 bottom
C278  47uF  [CC1206]  154.18 118.57 270 top
C279  47uF  [CC1206]  128.52 127.21 270 bottom
C280  47uF  [CC1206]  128.52 121.49 90 bottom
C281  4.7uF  [SM-7351-CAP-0603]  146.3 129.62 90 bottom
C282  4.7uF  [SM-7351-CAP-0603]  149.35 123.27 0 bottom
C283  4.7uF  [SM-7351-CAP-0603]  149.35 125.05 0 bottom
C284  4.7uF  [SM-7351-CAP-0603]  133.22 128.78 180 bottom
C285  4.7uF  [SM-7351-CAP-0603]  140.72 117.43 270 bottom
C286  1uF  [CC0402]  110.74 92.66 90 bottom
C287  1uF  [CC0402]  108.58 92.66 90 bottom
C288  1uF  [CC0402]  109.04 80.04 0 bottom
C289  1uF  [CC0402]  115.57 73.23 0 bottom
C290  1uF  [CC0402]  106.43 92.66 90 bottom
C291  1uF  [CC0402]  108.25 79 0 bottom
C292  1uF  [CC0402]  118.24 76.54 270 bottom
C293  1uF  [CC0402]  104.39 92.66 90 bottom
C294  1uF  [CC0402]  102.54 76.26 270 bottom
C295  1uF  [CC0402]  102.87 67.9 270 bottom
C296  1uF  [CC0402]  101.73 67.9 270 bottom
C297  1uF  [CC0402]  94.11 82.73 180 bottom
C298  1uF  [CC0402]  91.34 82.76 180 bottom
C299  1uF  [CC0402]  88.47 84.08 180 bottom
C300  1uF  [CC0402]  94.36 79.76 180 bottom
C301  2.2uF  [CC0402]  141.48 135.97 90 top
C302  2.2uF  [CC0402]  139.7 130.38 90 bottom
C303  0.1uF  [CC0402]  48.64 24.64 270 top
C304  0.1uF  [CC0402]  46.61 38.23 90 top
C305  10uF  [CC0805]  21.46 30.82 270 bottom
C306  10uF  [CC0805]  21.59 36.02 180 bottom
C307  10uF  [CC0805]  25.78 30.82 270 bottom
C308  10000pF  [CC0402]  24.38 35.51 180 top
C309  10000pF  [CC0402]  27.43 31.58 270 bottom
C310  10000pF  [CC0402]  31.5 31.58 270 bottom
C311  150uF  [SM-7351-CAP-2917]  39.75 5.64 180 bottom
C313  0.1uF  [CC0402]  122.68 20.45 270 bottom
C314  0.1uF  [CC0402]  128.52 26.92 0 bottom
C315  10000pF  [CC0402]  77.22 114.89 90 bottom
C316  1uF  [CC0603]  139.95 13.21 180 top
C317  10uF  [CC0805]  148.08 120.86 0 bottom
C318  2.2uF  [CC0402]  140.46 132.92 0 bottom
C319  10000pF  [CC0402]  187.22 96.73 180 bottom
C320  10uF  [CC0805]  31.5 41.48 90 bottom
C321  10000pF  [CC0402]  34.8 36.66 0 top
C322  10000pF  [CC0402]  34.29 38.82 0 bottom
C323  4.7uF  [SM-7351-CAP-0805]  113.79 4.57 90 top
C324  10000pF  [CC0402]  34.29 39.83 0 bottom
C325  4.7uF  [SM-7351-CAP-0805]  103.89 9.02 0 bottom
C326  10000pF  [CC0402]  18.54 39.58 90 bottom
C327  10000pF  [CC0402]  98.17 86.8 90 bottom
C328  10000pF  [CC0402]  91.97 89.26 90 bottom
C329  10000pF  [CC0402]  98.27 81.21 270 bottom
C330  10000pF  [CC0402]  90.97 89.24 90 bottom
C331  10000pF  [CC0402]  96.62 86.29 180 bottom
C332  10000pF  [CC0402]  109.32 77.98 0 bottom
C333  10uF  [CC0805]  98.42 96.09 90 bottom
C334  10000pF  [CC0402]  101.6 78.82 270 bottom
C335  10000pF  [CC0402]  104.65 77.45 270 bottom
C336  10000pF  [CC0402]  102.62 78.82 270 bottom
C337  10000pF  [CC0402]  105.77 77.5 270 bottom
C338  10000pF  [CC0402]  105.92 80.78 0 bottom
C339  10000pF  [CC0402]  101.02 76.97 0 bottom
C340  10uF  [CC0805]  114.81 77.42 0 bottom
C341  10000pF  [CC0402]  102.41 85.53 90 bottom
C342  10000pF  [CC0402]  109.93 83.6 0 bottom
C343  10000pF  [CC0402]  102.41 83.42 270 bottom
C344  10000pF  [CC0402]  100.36 81.34 90 bottom
C345  10000pF  [CC0402]  99.31 81.34 90 bottom
C346  10000pF  [CC0402]  97.1 76.54 270 bottom
C347  10uF  [CC0805]  89.66 75.34 180 bottom
C348  10000pF  [CC0402]  95.02 78.14 90 bottom
C349  10000pF  [CC0402]  99.24 76.54 270 bottom
C350  1uF  [CC0402]  96.9 129.24 180 top
C351  10000pF  [CC0402]  96.06 76.54 270 bottom
C352  10000pF  [CC0402]  109.32 76.97 0 bottom
C353  10000pF  [CC0402]  107.06 83.88 270 bottom
C354  10uF  [CC0805]  116.2 99.78 90 bottom
C355  10000pF  [CC0402]  105.05 83.98 270 bottom
C356  10000pF  [CC0402]  107.42 85.45 0 bottom
C357  10000pF  [CC0402]  107.42 86.49 0 bottom
C358  10000pF  [CC0402]  105.79 88.09 180 bottom
C359  10000pF  [CC0402]  103.96 86.29 180 bottom
C360  10000pF  [CC0402]  112.27 79.99 0 bottom
C361  10uF  [CC0805]  84.33 93.55 180 bottom
C362  10000pF  [CC0402]  109.96 85.76 0 bottom
C363  10000pF  [CC0402]  101.24 86.82 90 bottom
C364  10000pF  [CC0402]  112.26 78.94 0 bottom
C365  10000pF  [CC0402]  109.96 86.9 0 bottom
C367  10000pF  [CC0402]  108.46 88.8 90 bottom
C368  10000pF  [CC0402]  102.54 74.22 270 bottom
C369  10000pF  [CC0402]  117.47 79.08 0 bottom
C370  10000pF  [CC0402]  117.47 80.09 0 bottom
C371  10000pF  [CC0402]  107.04 76.79 270 bottom
C372  10000pF  [CC0402]  98.39 74.22 270 bottom
C373  10000pF  [CC0402]  101.35 89.24 90 bottom
C374  10000pF  [CC0402]  100.46 74.22 270 bottom
C375  10uF  [CC0805]  99.54 70.03 0 bottom
C376  10000pF  [CC0402]  96.53 73.9 270 bottom
C377  10000pF  [CC0402]  101.5 74.22 270 bottom
C378  10000pF  [CC0402]  99.2 72.25 0 bottom
C379  10000pF  [CC0402]  102.36 89.24 90 bottom
C380  10000pF  [CC0402]  101.37 83.7 90 bottom
C381  10000pF  [CC0402]  100.58 78.82 270 bottom
C382  2.2uF  [CC0402]  136.91 130.64 180 bottom
C383  2.2uF  [CC0402]  137.01 129.39 180 bottom
C384  10uF  [CC0805]  120.78 86.19 0 bottom
C385  10000pF  [CC0402]  111.38 75.87 0 bottom
C386  10000pF  [CC0402]  107.37 88.8 90 bottom
C387  10uF  [CC0805]  99.69 90.04 90 bottom
C388  10000pF  [CC0402]  103.66 81.34 270 bottom
C389  10000pF  [CC0402]  102.41 81.34 90 bottom
C390  0.1uF  [CC0402]  94.36 85.04 90 bottom
C391  10000pF  [CC0402]  93.22 85.04 90 bottom
C392  2.2uF  [CC0402]  142.75 124.03 180 bottom
C393  0.1uF  [CC0402]  91.31 81.53 180 bottom
C394  10000pF  [CC0402]  96.75 81.67 180 bottom
C395  10uF  [CC0805]  104.14 97.36 90 bottom
C396  10uF  [CC0805]  87.45 89.34 90 bottom
C399  2.2uF  [CC0402]  141.22 131.02 180 bottom
C400  10000pF  [CC0402]  96.22 84.92 180 bottom
C401  10000pF  [CC0402]  97.71 83.43 0 bottom
C402  2.2uF  [CC0402]  137.67 133.43 90 bottom
C403  10000pF  [CC0402]  88.49 82.78 180 bottom
C404  10000pF  [CC0402]  91.29 84.13 180 bottom
C405  10000pF  [CC0402]  103.38 89.24 90 bottom
C406  10000pF  [CC0402]  96.93 89.13 90 bottom
C407  1uF  [CC0402]  144.53 101.05 180 top
C408  10000pF  [CC0402]  147.57 96.47 0 top
C409  10000pF  [CC0402]  147.57 97.49 0 top
C410  10000pF  [CC0402]  149.35 93.17 90 top
C411  100uF  [SM-7351-CAP-SMDCAN]  182.52 126.57 270 bottom
C412  100uF  [SM-7351-CAP-SMDCAN]  182.52 126.57 270 top
C413  10uF  [CC0805]  89.66 77.37 180 bottom
C414  10uF  [CC0805]  115.7 86.16 0 bottom
C415  0.1uF  [CC0402]  153.09 106.14 270 bottom
C416  4.7uF  [SM-7351-CAP-0603]  151.82 106.14 270 bottom
C417  0.1uF  [CC0402]  156.01 103.47 270 bottom
C418  22uF  [CC0805]  160.6 107.87 90 bottom
C419  22uF  [CC0805]  160.6 107.87 90 top
C420  10000pF  [CC0402]  172.97 74.38 90 top
C421  1uF  [CC0603]  186.33 81.74 180 bottom
C422  10000pF  [CC0402]  105.79 90.12 180 bottom
C423  10000pF  [CC0402]  105.79 89.11 180 bottom
C424  10000pF  [CC0402]  151.89 98.13 270 top
C425  10000pF  [CC0402]  172.97 69.02 270 top
C426  10000pF  [CC0402]  175.13 81.08 270 bottom
C427  10000pF  [CC0402]  61.21 22.86 180 top
C428  10000pF  [CC0402]  68.71 13.21 0 top
C429  10000pF  [CC0402]  59.26 15.47 180 top
C430  10000pF  [CC0402]  97.79 6.1 180 top
C431  0.1uF  [CC0402]  115.44 4.19 90 top
C432  0.1uF  [CC0402]  129.67 7.11 270 top
C433  10uF  [CC0805]  115.95 8 90 bottom
C434  0.1uF  [CC0402]  102.49 12.83 90 bottom
C435  10uF  [CC1206]  133.1 8 270 top
C436  0.1uF  [CC0402]  60.71 40.51 270 top
C437  0.1uF  [CC0402]  59.69 40.51 270 top
C438  0.1uF  [CC0402]  74.83 75.9 0 top
C439  0.1uF  [CC0402]  74.83 76.92 0 top
C440  100uF  [SM-7351-CAP-SMDCAN]  117.6 53.8 90 bottom
C441  100uF  [SM-7351-CAP-SMDCAN]  70.1 65.49 90 bottom
C442  1uF  [CC0402]  103.63 78.82 270 bottom
C443  10000pF  [CC0402]  169.34 81.41 180 bottom
C444  10000pF  [CC0402]  172.57 64.09 270 bottom
C445  1uF  [CC0402]  101.37 81.34 90 bottom
C446  1uF  [CC0402]  90.55 86.11 90 bottom
C447  1uF  [CC0402]  94.11 81.66 180 bottom
C448  10000pF  [CC0402]  171.7 67.65 90 bottom
C449  0.1uF  [CC0402]  174.14 5.72 270 bottom
C450  10uF  [SM-7351-CAP-0603]  143.13 127.46 270 bottom
C451  10000pF  [CC0402]  141.86 127.46 270 bottom
C452  10uF  [SM-7351-CAP-0603]  139.19 117.43 270 bottom
C453  10000pF  [CC0402]  132.97 127.36 180 bottom
C454  0.1uF  [CC0402]  66.93 75.52 90 top
C455  0.1uF  [CC0402]  105.28 137.75 0 top
C456  0.1uF  [CC0402]  112.65 137.62 0 top
C457  0.1uF  [CC0402]  120.78 137.62 0 top
C458  10uF  [CC0805]  157.86 126.83 180 bottom
C459  1uF  [CC0603]  157.57 126.74 180 top
C460  0.1uF  [CC0402]  156.18 120.52 270 top
C461  10uF  [CC0805]  162.85 120.69 270 top
C462  10uF  [CC0805]  162.85 125.01 90 top
C463  1.1nF  [SM-7351-CAP-0603]  158.24 115.91 0 top
C464  2.2uF  [SM-7351-CAP-0805]  144.53 134.45 90 bottom
C465  2.2uF  [SM-7351-CAP-0805]  142.62 134.45 90 bottom
C466  2.2uF  [SM-7351-CAP-0805]  132.33 133.05 270 bottom
C467  2.2uF  [SM-7351-CAP-0805]  134.49 133.05 270 bottom
C468  2.2uF  [SM-7351-CAP-0805]  136.53 118.95 180 bottom
C469  10000pF  [CC0402]  57.53 37.72 270 top
C470  10000pF  [CC0402]  57 43.66 180 top
C471  2.2uF  [SM-7351-CAP-0805]  70.61 108.03 180 bottom
C472  2.2uF  [SM-7351-CAP-0805]  75.44 114.13 90 bottom
C473  47uF  [CT7343-31]  74.8 89.41 270 bottom
C474  47uF  [CT7343-31]  117.86 89.74 0 bottom
C475  47uF  [CT7343-31]  128.02 113.49 90 bottom
C476  2.2uF  [SM-7351-CAP-0402]  158.8 106.27 270 bottom
C477  0.1uF  [CC0402]  65.91 40.51 270 top
C478  0.1uF  [CC0402]  66.93 40.51 270 top
C479  2.2uF  [SM-7351-CAP-0805]  97.92 131.78 0 top
C480  10000pF  [CC0402]  153.16 95.71 180 top
C481  10000pF  [CC0402]  153.16 94.57 180 top
C482  10000pF  [CC0402]  149.73 98 270 top
C483  10uF  [CC0805]  84.33 96.09 180 bottom
C484  1uF  [CC0402]  150.62 101.05 0 top
C485  10000pF  [CC0402]  96.14 92.79 0 bottom
C486  10000pF  [CC0402]  96.14 91.78 0 bottom
C487  10000pF  [CC0402]  96.14 90.76 0 bottom
C488  10000pF  [CC0402]  146.43 52.53 0 top
C489  10000pF  [CC0402]  141.1 52.53 180 top
C490  10000pF  [CC0402]  144.02 52.53 180 top
C491  10000pF  [CC0402]  139.07 52.53 0 top
C492  22uF  [CC0805]  147.96 56.72 0 top
C493  10000pF  [CC0402]  137.03 52.53 0 top
C494  10000pF  [CC0402]  134.75 52.53 0 top
C495  10000pF  [CC0402]  135.26 48.09 270 top
C496  10000pF  [CC0402]  138.81 47.58 180 top
C497  10000pF  [CC0402]  136.78 48.6 0 top
C498  10000pF  [CC0402]  138.81 48.6 180 top
C499  10000pF  [CC0402]  140.08 43.64 180 top
C500  10000pF  [CC0402]  138.05 43.64 0 top
C501  10000pF  [CC0402]  135.64 43.64 180 top
C502  10000pF  [CC0402]  133.73 45.55 270 top
C503  0.1uF  [CC0402]  139.95 55.71 270 bottom
C504  0.1uF  [CC0402]  140.97 55.71 90 bottom
C505  0.1uF  [CC0402]  138.3 55.71 90 bottom
C506  10000pF  [CC0402]  133.73 60.79 270 top
C507  10000pF  [CC0402]  138.05 58.88 0 top
C508  10000pF  [CC0402]  140.08 58.88 180 top
C509  10000pF  [CC0402]  144.53 58.88 0 top
C510  22uF  [CC0805]  134.24 56.22 180 top
C511  10000pF  [CC0402]  134.75 67.77 0 top
C512  10000pF  [CC0402]  144.02 67.77 180 top
C513  10000pF  [CC0402]  146.43 67.77 0 top
C514  10000pF  [CC0402]  135.64 58.88 180 top
C515  10000pF  [CC0402]  139.45 67.77 0 top
C516  10000pF  [CC0402]  137.03 67.77 0 top
C517  10000pF  [CC0402]  146.56 58.88 0 top
C518  10000pF  [CC0402]  135.76 63.84 180 top
C519  10000pF  [CC0402]  142.11 58.88 0 top
C520  10000pF  [CC0402]  138.81 62.82 180 top
C521  0.1uF  [CC0402]  139.95 70.95 270 bottom
C522  0.1uF  [CC0402]  140.97 70.95 90 bottom
C523  0.1uF  [CC0402]  142.75 60.58 180 top
C524  10000pF  [CC0402]  104.39 74.25 270 bottom
C525  0.1uF  [CC0402]  151 68.28 180 top
C526  0.1uF  [CC0402]  149.1 70.95 270 bottom
C527  0.1uF  [CC0402]  150.11 70.95 270 bottom
C528  0.1uF  [CC0402]  151.51 56.6 270 top
C529  0.1uF  [CC0402]  139.95 70.95 270 top
C530  0.1uF  [CC0402]  151 67.26 180 bottom
C531  0.1uF  [CC0402]  161.54 60.79 0 bottom
C532  10uF  [CC0805]  164.21 55.45 0 bottom
C533  10pF  [SM-7351-CAP-0402]  158.37 60.66 90 bottom
C534  10uF  [CC0805]  155.32 59.26 90 top
C535  10uF  [CC0805]  157.35 59.26 90 top
C536  10uF  [CC0805]  155.32 59.26 90 bottom
C537  0.1uF  [CC0402]  156.84 58.37 90 bottom
C538  0.1uF  [CC0402]  141.99 70.95 270 bottom
C539  0.1uF  [CC0402]  151 58.12 180 top
C540  10uF  [CC0805]  155.32 55.33 270 bottom
C541  10uF  [CC0805]  155.32 55.33 270 top
C542  0.1uF  [CC0402]  156.84 56.09 270 bottom
C543  0.001uF  [SM-7351-CAP-0402]  159.51 51.64 270 bottom
C544  0.001uF  [SM-7351-CAP-0402]  158.37 54.18 270 bottom
C545  150uF  [SM-7351-CAP-2917]  11.73 44.96 0 top
C546  4.7uF  [SM-7351-CAP-0603]  6.6 38.44 270 bottom
C547  10000pF  [CC0402]  8.76 41.23 0 top
C548  10000pF  [CC0402]  120.27 81.74 0 bottom
C549  0.1uF  [CC0402]  65.41 51.26 0 top
C550  10000pF  [CC0402]  104.9 71.46 270 bottom
C551  10000pF  [CC0402]  106.93 70.06 270 bottom
C552  10000pF  [CC0402]  105.92 74.25 180 bottom
C553  10000pF  [CC0402]  105.92 73.23 180 bottom
C554  0.1uF  [CC0402]  37.59 23.37 270 bottom
C555  0.1uF  [CC0402]  36.58 23.37 270 bottom
C556  0.1uF  [CC0402]  53.98 24.64 270 top
C557  0.1uF  [CC0402]  30.23 17.14 0 bottom
C558  0.001uF  [SM-7351-CAP-0402]  30.23 15.88 0 bottom
C559  0.1uF  [CC0402]  5.46 32.77 180 top
C560  0.001uF  [SM-7351-CAP-0402]  5.46 34.04 180 top
C562  2.2uF  [CC0402]  144.53 122.94 270 bottom
C563  0.1uF  [CC0402]  81.91 82.8 180 bottom
C564  10000pF  [CC0402]  99.82 83.44 0 bottom
C565  1uF  [CC0402]  81.91 81.41 180 bottom
C566  0.1uF  [CC0402]  97.92 78.08 0 bottom
C567  10000pF  [CC0402]  81.28 79.25 180 bottom
C568  1uF  [CC0402]  81.28 78.23 180 bottom
C569  10000pF  [CC0402]  161.8 51.18 90 bottom
C570  DNI  [SM-7351-CAP-0402]  161.8 48.89 270 bottom
C571  10000pF  [CC0402]  162.94 40.77 270 bottom
C572  10000pF  [CC0402]  85.98 68.2 270 bottom
C573  10000pF  [CC0402]  91.95 72.77 90 bottom
C574  10000pF  [CC0402]  109.98 84.71 0 bottom
C575  10000pF  [CC0402]  114.81 75.56 0 bottom
C576  10000pF  [CC0402]  88.65 81.66 180 bottom
C577  10000pF  [CC0402]  114.81 74.55 0 bottom
C578  2.2uF  [SM-7351-CAP-0805]  131.79 130.33 180 bottom
C579  47uF  [CC1206]  141.81 143.32 180 top
C580  DNI  [SM-7351-CAP-0402]  155.23 138.16 0 top
D1  -  [SK1545]  167.16 108.03 90 bottom
D2  SMCJ5.0A  [SMCJ26CA]  167.67 114.89 90 top
D3  MMSD103T1  [SOD-123]  39.5 112.86 0 bottom
D4  MMSD103T1  [SOD-123]  61.21 112.86 0 bottom
D5  Green LED  [SM_LED_0805]  179.35 37.46 0 top
D6  Green LED  [SM_LED_0805]  179.35 35.31 0 top
D7  Green LED  [SM_LED_0805]  179.35 33.15 0 top
D8  Green LED  [SM_LED_0805]  179.35 30.99 0 top
D9  Green LED  [SM_LED_0805]  179.35 28.83 0 top
D10  Green LED  [SM_LED_0805]  179.35 26.67 0 top
D11  Green LED  [SM_LED_0805]  179.35 24.51 0 top
D12  Green LED  [SM_LED_0805]  179.35 22.35 0 top
D13  Green LED  [SM_LED_0805]  162.74 91.32 180 top
D14  MBR0520LT1G  [DIO_SOD-123]  118.62 5.33 270 bottom
D15  MBR0520LT1G  [DIO_SOD-123]  118.62 11.18 90 bottom
D16  Red_Green_Blue_LED  [LED-SM1210]  10.67 4.32 270 top
D17  Red_Green_Blue_LED  [LED-SM1210]  14.86 4.32 270 top
D18  Red_Green_Blue_LED  [LED-SM1210]  18.67 4.32 270 top
D19  Red_Green_Blue_LED  [LED-SM1210]  22.61 4.32 270 top
D20  PMEG2010  [DFN1006D-2]  160.91 123.78 90 top
D22  Red_Green_Blue_LED  [LED-SM1210]  72.9 100.16 270 top
D23  Red_Green_Blue_LED  [LED-SM1210]  69.47 100.16 270 top
D24  TLVH431  [SOT23-3-44M]  38.86 93.6 90 bottom
D25  TLVH431  [SOT23-3-44M]  116.97 128.27 180 bottom
F1  Fuse 8A  [FUSE-0154]  167.51 104.6 180 top
FB1  10 OHM  [FB0603]  48.26 121.75 180 bottom
FB2  10 OHM  [FB0603]  44.2 121.62 180 bottom
FB3  10 OHM  [FB0603]  44.2 118.95 180 bottom
FB4  10 OHM  [FB0603]  44.2 124.29 180 bottom
FB5  10 OHM  [FB0603]  73.02 110.95 180 top
FB6  10 OHM  [FB0603]  65.91 121.87 180 top
FB7  10 OHM  [FB0603]  66.04 119.08 180 top
FB8  10 OHM  [FB0603]  65.91 124.41 180 top
FB9  220OHM2.2A  [SM-7351-IND-0603]  180.37 16.38 180 top
FB10  220OHM2.2A  [SM-7351-IND-0603]  163.75 83.32 90 bottom
FB11  220OHM2.2A  [SM-7351-IND-0603]  163.75 79 270 bottom
FB12  150OHM800mA  [SM-7351-IND-0805]  183.79 20.07 180 bottom
FB13  150OHM800mA  [SM-7351-IND-0805]  23.62 30.82 270 bottom
FB19  150OHM800mA  [SM-7351-IND-0805]  154.69 98.13 180 top
J1  Power Jack RAPC712  [RAPC712]  175.99 111.76 180 top
J1_1  Receptacle 4x1  [HDR4X1RA-108M]  180.83 3.57 270 top
J2  DNI Connector_Screwdown  [CONN_OSTTC02]  186.47 109.35 90 top
J3  RJ-45 10_100Mb  [CNRJ45-1X1WLED]  17.15 135.26 270 top
J4  HEADER 5  [HEADER_5X1]  27.05 71.35 0 top
J5  RJ-45 10_100Mb  [CNRJ45-1X1WLED]  17.15 111.12 270 top
J6  RJ-45 10_100Mb  [CNRJ45-1X1WLED]  17.15 87 270 top
J7  HEADER 5  [HEADER_5X1]  26.92 65.13 0 top
J8  RJ-45 10_100Mb  [CNRJ45-1X1WLED]  17.15 62.23 270 top
J9  HEADER 12x2  [HDR2X12]  159.03 137.11 90 top
J10  RJ-45 Gigabit  [CNRJ45-1X1WLED-598M]  39.24 132.51 180 top
J12  RJ-45 Gigabit  [CNRJ45-1X1WLED-598M]  60.96 132.51 180 top
J14  Conn_DB9F  [NORCOMP_DB9F_SMD]  94.15 2.14 180 top
J15  503182-1852_CUS  [MOLEX_5031821852]  90.69 143.66 0 top
J16  XF2M-3215-1A  [CNXF2M-3215-1A]  82.35 121.65 90 bottom
J17  XF2M-0615-1A  [OMRON_XF2M-0615-1A]  51.87 88.26 90 bottom
J18  MIPI JTAG 60pin  [CNQSH030DA]  184.3 89.87 270 top
J19  USB_MicroAB  [ZX62-AB-5PA]  186.38 14.4 90 top
J21  Header_30x2_Female  [HDR2X30-2MM-177M]  101.35 147.02 0 top
J22  10018783-11000TLF  [CN_10018783-11000TLF]  45.63 33.16 0 top
J23  USB3_0_StdA  [CN_LPAF3102NL]  36.24 13.78 0 top
J24  HDMIConnA  [SMD_HDMIA_RA]  62.4 3.58 0 top
J37  Header 15x2 Female  [HDR2X15-344M]  184.94 59.05 270 top
J38  HEADER 5  [HEADER_5X1]  152.78 14.22 270 top
J39  HEADER 3  [HEADER_3X1]  158.75 9.14 270 top
J40  HEADER 2  [HEADER_2X1]  69.34 74.25 0 top
J41  HEADER 2  [HEADER_2X1]  106.55 140.04 90 top
J42  HEADER 2  [HEADER_2X1]  114.05 139.91 90 top
J43  HEADER 2  [HEADER_2X1]  122.05 139.91 90 top
J44  DNI  [HEADER_2X1]  83.57 106.89 0 top
J45  USB_MicroAB  [ZX62-AB-5PA]  4.12 41.1 90 bottom
J46  HEADER 4  [HDR1X4-330M]  168.53 11.51 0 top
J47  HEADER 2  [HEADER_2X1]  64.26 48.85 270 top
J49  HEADER 2  [HEADER_2X1]  50.67 43.05 270 top
J50  HEADER 2  [HEADER_2X1]  14.61 40.89 180 top
J51  HEADER 2  [HEADER_2X1]  56.68 67.34 90 top
L1  4.7uH  [VLCF5020T]  77.98 143.97 270 top
L2  DA2304-AL  [DA2304]  127.76 8.25 180 bottom
L3  NFM21PC474  [FILT-NFM21PC]  28.7 41.23 270 bottom
L11  ACM2012  [ACM2012H]  45.72 24.13 270 bottom
L12  1.0uH  [IND_IHLP1616AB]  151 132.67 0 top
L13  1.0uH  [IND_IHLP1616AB]  151 128.1 0 top
L14  1.0uH  [IND_IHLP1616AB]  151 123.53 0 top
L15  1.0uH  [IND_IHLP1616AB]  128.52 127.21 90 top
L16  1.0uH  [IND_IHLP1616AB]  128.52 121.49 270 top
L17  1.0uH  [IND_IHLP1616AB]  135.51 114.38 270 top
L18  1.0uH  [IND_IHLP1616AB]  128.52 132.92 90 top
L19  1.0uH  [IND_IHLP1616AB]  144.4 114.38 270 top
L20  1.0uH  [IND_IHLP1616AB]  139.95 114.38 270 top
L21  NFM21PC474  [FILT-NFM21PC]  112.73 82.55 90 bottom
L22  4.7uH  [IND_SRN5040]  155.12 111.47 0 bottom
L24  NFM21PC474  [FILT-NFM21PC]  108.84 81.87 180 bottom
L25  NFM21PC474  [FILT-NFM21PC]  88.01 85.93 0 bottom
L26  NFM21PC474  [FILT-NFM21PC]  87.88 79.63 0 bottom
L28  3.3uH  [VLCF5020T]  158.88 131.53 0 top
L29  DLW21SN900HQ2L  [FILT-DLW21S]  55.88 20.32 270 top
L30  DLW21SN900HQ2L  [FILT-DLW21S]  58.42 20.32 270 top
L31  DLW21SN900HQ2L  [FILT-DLW21S]  70.87 20.45 270 top
L32  DLW21SN900HQ2L  [FILT-DLW21S]  73.41 20.45 270 top
L33  ACM2012  [ACM2012H]  9.14 40.89 180 bottom
L34  NFM21PC474  [FILT-NFM21PC]  85.47 83.19 180 bottom
L35  NFM21PC474  [FILT-NFM21PC]  80.14 76.07 0 bottom
NOREF  -  []  138.3 48.33 90 top
NOREF#2  -  []  46.25 101.54 90 top
NOREF#3  -  []  81.4 82.54 90 top
NOREF#4  -  []  23.24 123.41 0 top
NOREF#5  -  []  178.21 16.38 90 top
NOREF#6  -  []  117.97 76.02 0 top
NOREF#7  -  []  122.94 19.93 90 top
NOREF#8  -  []  131.31 143.47 0 top
NOREF#9  -  []  172.51 80.64 0 top
NOREF#10  -  []  109.58 75.46 90 top
NOREF#11  -  []  103.37 78.31 0 top
NOREF#12  -  []  112.78 21.08 90 top
NOREF#13  -  []  167.68 70.99 90 top
NOREF#14  -  []  115.18 4.7 0 top
NOREF#15  -  []  109.73 17.52 90 top
NOREF#16  -  []  96.91 25.78 90 top
NOREF#17  -  []  97.04 32.89 90 top
NOREF#18  -  []  175.41 45.2 0 top
NOREF#19  -  []  74.32 75.64 0 top
NOREF#20  -  []  121.29 33.9 90 top
NOREF#21  -  []  96.51 34.92 0 top
NOREF#22  -  []  96.11 86.03 0 top
NOREF#23  -  []  129.04 26.66 90 top
NOREF#24  -  []  120.78 81.48 90 top
NOREF#25  -  []  90.54 73.28 0 top
NOREF#26  -  []  186.71 96.47 0 top
NOREF#27  -  []  154.35 85.09 90 top
NOREF#28  -  []  65.65 40 0 top
NOREF#29  -  [unnamed#2]  130.56 117.18 0 top
NOREF#30  -  []  161.54 51.69 0 top
NOREF#31  -  []  151.13 100.78 90 top
NOREF#32  -  []  140.22 55.19 90 top
NOREF#33  -  []  107.3 76.28 90 top
NOREF#34  -  []  162.04 38.57 0 top
NOREF#35  -  []  90.29 36.44 90 top
NOREF#36  -  []  106.42 18.04 0 top
NOREF#37  -  []  164.38 85.47 0 top
NOREF#38  -  []  140.71 130.76 90 top
NOREF#39  -  []  155.31 23.95 90 top
NOREF#40  -  []  48.87 85.01 90 top
NOREF#41  -  []  98.35 148.45 90 top
NOREF#42  -  []  98.93 39.25 0 top
NOREF#43  -  []  93.85 129.5 0 top
NOREF#44  -  []  34.15 93.93 0 top
NOREF#45  -  []  34.79 77.04 90 top
NOREF#46  -  []  171.46 17.73 90 top
NOREF#47  -  []  138.55 52.27 0 top
NOREF#48  -  []  141.74 135.46 90 top
NOREF#49  -  []  114.3 75.83 0 top
NOREF#50  -  []  133.47 45.03 90 top
NOREF#51  -  []  105.5 76.99 0 top
NOREF#52  -  []  100.45 129.49 0 top
NOREF#53  -  []  150.49 68.02 90 top
NOREF#54  -  []  108.81 77.23 0 top
NOREF#55  -  []  110.99 31.61 90 top
NOREF#56  -  []  136.39 130.37 0 top
NOREF#57  -  []  127.88 24.27 0 top
NOREF#58  -  []  101.48 127.45 90 top
NOREF#59  -  []  117.99 79.83 90 top
NOREF#60  -  []  31.49 94.82 0 top
NOREF#61  -  []  100.98 87.33 0 top
NOREF#62  -  []  19.82 71.95 90 top
NOREF#63  -  []  164.91 85.47 90 top
NOREF#64  -  []  62.6 120.35 0 top
NOREF#65  -  []  34.79 52.27 0 top
NOREF#66  -  []  34.8 38.55 90 top
NOREF#67  -  []  136.39 130.37 90 top
NOREF#68  -  []  93.01 72.69 0 top
NOREF#69  -  []  87.98 82.52 0 top
NOREF#70  -  []  25.52 56.71 90 top
NOREF#71  -  []  89.03 29.96 90 top
NOREF#72  -  []  25.4 103.07 90 top
NOREF#73  -  []  93.09 75.31 90 top
NOREF#74  -  []  103.12 89.75 0 top
NOREF#75  -  []  85.46 35.94 90 top
NOREF#76  -  []  128.14 46.6 0 top
NOREF#77  -  []  146.94 67.51 90 top
NOREF#78  -  []  93.59 82.47 90 top
NOREF#79  -  [unnamed#2]  62.48 114 0 top
NOREF#80  -  []  170.59 125.55 90 top
NOREF#81  -  []  -29.48 156.9 0 top
NOREF#82  -  []  149.47 97.49 90 top
NOREF#83  -  []  105.53 37.47 0 top
NOREF#84  -  []  149.85 70.43 0 top
NOREF#85  -  []  105.28 87.83 0 top
NOREF#86  -  []  65.78 140.67 0 top
NOREF#87  -  []  139.69 70.43 90 top
NOREF#88  -  []  139.69 70.43 0 top
NOREF#89  -  []  151.25 56.08 0 top
NOREF#90  -  []  56.09 89.57 0 top
NOREF#91  -  []  46.87 37.71 90 top
NOREF#92  -  []  111.75 32.89 0 top
NOREF#93  -  [unnamed#2]  29.74 125.66 0 top
NOREF#94  -  []  96.79 73.39 90 top
NOREF#95  -  []  138.56 58.62 90 top
NOREF#96  -  []  141.72 70.43 0 top
NOREF#97  -  []  94.1 84.53 90 top
NOREF#98  -  []  146.94 52.27 90 top
NOREF#99  -  []  104.65 39.23 90 top
NOREF#100  -  []  110.87 76.14 0 top
NOREF#101  -  []  175.41 47.74 0 top
NOREF#102  -  []  54.49 94.95 90 top
NOREF#103  -  []  25.4 85.29 90 top
NOREF#104  -  []  81.27 36.95 0 top
NOREF#105  -  []  106.42 17.52 90 top
NOREF#106  -  []  76.19 80.85 90 top
NOREF#107  -  []  93.59 81.4 90 top
NOREF#108  -  []  37.85 22.86 90 top
NOREF#109  -  []  175.41 52.82 0 top
NOREF#110  -  []  4.95 32.5 90 top
NOREF#111  -  []  17.65 138.38 90 top
NOREF#112  -  []  101.48 128.47 90 top
NOREF#113  -  []  49.65 117.8 90 top
NOREF#114  -  []  111.76 80.25 0 top
NOREF#115  -  []  101.11 83.19 90 top
NOREF#116  -  []  93.09 73.96 90 top
NOREF#117  -  []  111.62 28.96 0 top
NOREF#118  -  []  95.37 123.9 90 top
NOREF#119  -  []  105.28 88.85 0 top
NOREF#120  -  []  160.46 88.27 90 top
NOREF#121  -  []  90.8 81.27 0 top
NOREF#122  -  []  31.49 52.27 90 top
NOREF#123  -  []  90.29 32.9 0 top
NOREF#124  -  []  98.53 80.7 90 top
NOREF#125  -  []  148.09 97.23 90 top
NOREF#126  -  []  155.11 78.1 90 top
NOREF#127  -  []  102.35 78.31 0 top
NOREF#128  -  []  108.33 28.44 0 top
NOREF#129  -  []  100.09 80.82 90 top
NOREF#130  -  []  59.94 100.03 0 top
NOREF#131  -  []  25.4 83.13 90 top
NOREF#132  -  []  172.71 68.5 90 top
NOREF#133  -  []  89.41 39.23 90 top
NOREF#134  -  []  100.72 73.71 90 top
NOREF#135  -  []  88.01 30.49 0 top
NOREF#136  -  []  20.7 120.61 0 top
NOREF#137  -  []  164.47 40.25 90 top
NOREF#138  -  []  166.92 88.27 0 top
NOREF#139  -  []  99.5 76.02 90 top
NOREF#140  -  []  142.24 123.77 90 top
NOREF#141  -  []  96.89 69.93 0 top
NOREF#142  -  []  97.4 78.34 0 top
NOREF#143  -  []  68.19 106.64 0 top
NOREF#144  -  []  104.64 70.94 0 top
NOREF#145  -  []  142.99 84.45 0 top
NOREF#146  -  []  76.19 83.91 0 top
NOREF#147  -  []  25.4 60.52 90 top
NOREF#148  -  []  118.5 76.02 90 top
NOREF#149  -  []  152.65 95.45 90 top
NOREF#150  -  []  31.88 118.18 90 top
NOREF#151  -  []  112.78 79.73 90 top
NOREF#152  -  []  97.04 34.92 90 top
NOREF#153  -  []  160.61 78.87 90 top
NOREF#154  -  []  127.76 24.5 0 top
NOREF#155  -  []  150.49 67 0 top
NOREF#156  -  []  90.29 86.62 0 top
NOREF#157  -  []  112.28 34.92 90 top
NOREF#158  -  []  90.81 33.9 90 top
NOREF#159  -  []  115.19 38.73 90 top
NOREF#160  -  []  22.34 132.17 0 top
NOREF#161  -  []  108.81 78.25 0 top
NOREF#162  -  []  93.59 82.47 0 top
NOREF#163  -  [unnamed#2]  172.26 88.78 0 top
NOREF#164  -  []  165.78 79.24 0 top
NOREF#165  -  []  25.4 62.56 90 top
NOREF#166  -  []  153.32 111.47 0 top
NOREF#167  -  []  133.47 60.27 0 top
NOREF#168  -  []  96.65 92.53 90 top
NOREF#169  -  []  129.4 6.6 0 top
NOREF#170  -  []  121.29 137.36 90 top
NOREF#171  -  []  129.4 6.6 90 top
NOREF#172  -  []  62.48 121.36 0 top
NOREF#173  -  []  93.09 75.31 0 top
NOREF#174  -  [unnamed#2]  123.83 22.1 0 top
NOREF#175  -  []  108.56 75.98 0 top
NOREF#176  -  []  140.71 55.19 90 top
NOREF#177  -  []  172.51 78.1 0 top
NOREF#178  -  []  101.08 88.72 90 top
NOREF#179  -  []  112.14 137.36 0 top
NOREF#180  -  []  30.74 16.88 90 top
NOREF#181  -  []  134.23 52.27 0 top
NOREF#182  -  []  106.9 85.71 0 top
NOREF#183  -  []  69.59 139.14 0 top
NOREF#184  -  []  116.08 72.97 90 top
NOREF#185  -  []  49.65 122.52 0 top
NOREF#186  -  []  110.75 71.88 90 top
NOREF#187  -  []  97.42 69.93 90 top
NOREF#188  -  []  81.27 34.92 0 top
NOREF#189  -  []  98.98 76.02 0 top
NOREF#190  -  []  81.8 36.95 90 top
NOREF#191  -  []  168.83 81.15 90 top
NOREF#192  -  []  112.28 32.89 90 top
NOREF#193  -  []  26.53 49.35 90 top
NOREF#194  -  []  46.35 38.74 0 top
NOREF#195  -  []  22.22 138.38 0 top
NOREF#196  -  []  134.39 29.4 0 top
NOREF#197  -  []  92.96 85.56 0 top
NOREF#198  -  []  92.96 84.53 90 top
NOREF#199  -  []  131.83 142.44 90 top
NOREF#200  -  []  108.96 33.4 0 top
NOREF#201  -  []  22.09 118.94 0 top
NOREF#202  -  []  91.69 73.28 0 top
NOREF#203  -  []  59.43 40 90 top
NOREF#204  -  []  140.71 71.46 0 top
NOREF#205  -  []  106.05 25.78 90 top
NOREF#206  -  []  100.45 130.5 0 top
NOREF#207  -  []  162.06 60.52 90 top
NOREF#208  -  []  56.49 43.4 90 top
NOREF#209  -  []  139.58 52.27 90 top
NOREF#210  -  []  160.9 38.57 0 top
NOREF#211  -  []  41.14 100.53 90 top
NOREF#212  -  []  168.46 88.27 90 top
NOREF#213  -  []  170.07 126.58 0 top
NOREF#214  -  [unnamed#2]  4.45 142.96 0 top
NOREF#215  -  []  181.5 98.9 0 top
NOREF#216  -  []  60.59 108.41 90 top
NOREF#217  -  []  105.28 89.86 0 top
NOREF#218  -  []  151.25 56.08 90 top
NOREF#219  -  []  138.3 63.08 0 top
NOREF#220  -  []  153.35 105.63 90 top
NOREF#221  -  []  183.04 16.38 90 top
NOREF#222  -  []  24.38 58.89 0 top
NOREF#223  -  []  95.37 124.42 0 top
NOREF#224  -  []  30.86 118.71 0 top
NOREF#225  -  []  28.57 80.61 0 top
